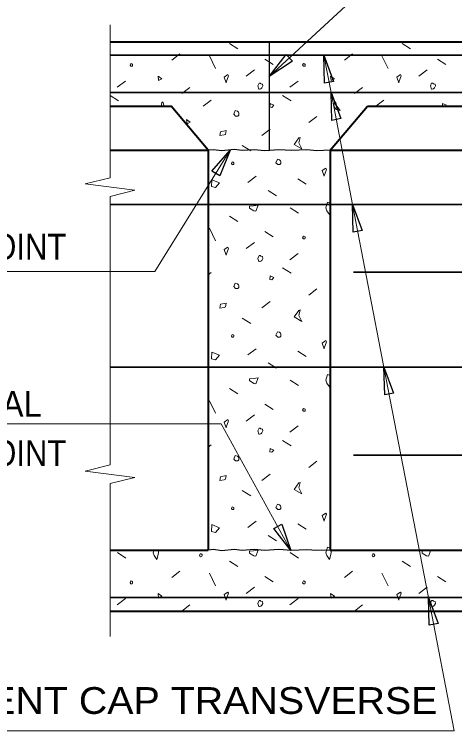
# Model space of a CAD drawing. Extents: x 0 to 34, y 0 to 23.4.
# Drawn here: x 12.452 to 15.025, y 15.614 to 19.798 of the extents above; entities that cross this region are included whole.
import ezdxf
from ezdxf.enums import TextEntityAlignment as Align

# ---------------------------------------------------------------- set-up
doc = ezdxf.new("R2010")
doc.units = 0
doc.header["$LTSCALE"] = 0.062
for name, color, linetype, lineweight in [('1', 7, 'Continuous', 40), ('3', 7, 'Continuous', 35), ('4', 7, 'Continuous', 13), ('7', 7, 'Continuous', 13)]:
    doc.layers.add(name, color=color, linetype=linetype, lineweight=lineweight)

msp = doc.modelspace()

# ---------------------------------------------------------------- linework, layer by layer
at = {"layer": '1', "lineweight": 13}
for p, q in [((13.0112, 18.84359), (13.0112, 19.73682)), ((13.0112, 17.16651), (13.0112, 18.73422)), ((13.0112, 16.16391), (13.0112, 17.05714))]:
    msp.add_line(p, q, dxfattribs=at)
at = {"layer": '1'}
for p, q in [((13.0112, 19.63786), (17.36536, 19.63786)), ((13.0112, 19.26182), (13.36745, 19.26182)), ((13.58516, 19.00453), (13.36745, 19.26182)), ((14.29766, 19.00453), (14.51536, 19.26182)), ((14.51536, 19.26182), (17.36536, 19.26182)), ((14.29766, 19.00667), (14.29766, 16.66911)), ((13.0112, 16.66911), (13.58516, 16.66911)), ((14.29766, 16.66911), (17.36536, 16.66911)), ((13.0112, 16.31286), (17.36536, 16.31286))]:
    msp.add_line(p, q, dxfattribs=at)
at = {"layer": '1', "lineweight": 25}
msp.add_line((13.94141, 19.63786), (13.94141, 19.00453), dxfattribs=at)
at = {"layer": '1'}
for points in [[(13.0112, 19.00453), (13.58516, 19.00453), (13.58516, 16.66911)], [(14.29766, 19.00453), (16.07891, 19.00453), (17.36536, 19.00453)]]:
    msp.add_lwpolyline(points, dxfattribs=at)
at = {"layer": '1', "lineweight": 25}
for points in [[(14.29766, 19.00453), (14.21839, 19.00125), (14.16151, 19.00667), (14.07125, 19.0025), (13.99667, 19.00693), (13.91625, 19.00151), (13.85344, 19.00714), (13.78281, 19.0025), (13.73573, 19.00786), (13.6651, 19.00078), (13.61604, 19.00714), (13.58516, 19.00453)], [(14.29766, 16.66911), (14.21839, 16.66583), (14.16151, 16.67125), (14.07125, 16.66708), (13.99667, 16.67151), (13.91625, 16.66609), (13.85344, 16.67172), (13.78281, 16.66708), (13.73573, 16.67245), (13.6651, 16.66536), (13.61604, 16.67172), (13.58516, 16.66911)]]:
    msp.add_lwpolyline(points, dxfattribs=at)
at = {"layer": '1', "lineweight": 13}
for points in [[(13.0112, 18.84359), (12.86536, 18.80714), (13.15703, 18.77068), (13.0112, 18.73422)], [(13.0112, 17.16651), (12.86536, 17.13005), (13.15703, 17.09359), (13.0112, 17.05714)]]:
    msp.add_lwpolyline(points, dxfattribs=at)
at = {"layer": '3'}
for p, q in [((13.0112, 19.5587), (17.36536, 19.5587)), ((13.0112, 19.34099), (17.36536, 19.34099)), ((17.36536, 18.68786), (13.0112, 18.68786)), ((17.36536, 18.29203), (14.43375, 18.29203)), ((17.36536, 17.73786), (13.0112, 17.73786)), ((17.36536, 17.22328), (14.43375, 17.22328)), ((13.0112, 16.39203), (17.36536, 16.39203))]:
    msp.add_line(p, q, dxfattribs=at)
at = {"layer": '4'}
for p, q in [((14.52495, 19.97521), (13.94141, 19.43542)), ((14.30255, 19.34099), (14.26052, 19.5587)), ((14.42844, 18.68786), (14.3025, 19.34099)), ((13.27292, 18.29536), (13.71349, 19.00453)), ((14.61161, 17.73786), (14.42839, 18.68786)), ((11.35625, 18.29536), (13.27292, 18.29536)), ((11.35625, 17.40693), (13.66078, 17.40693)), ((13.66078, 17.40693), (14.06828, 16.66724)), ((10.84479, 15.61406), (15.02104, 15.61406))]:
    msp.add_line(p, q, dxfattribs=at)
at = {"layer": '4', "lineweight": 25}
for points in [[(14.04073, 19.56365), (14.07698, 19.52448), (13.94141, 19.43542)], [(14.31698, 19.40661), (14.26464, 19.39656), (14.26052, 19.5587)], [(14.35896, 19.18891), (14.30661, 19.17885), (14.3025, 19.34099)], [(13.65172, 18.85453), (13.60641, 18.88271), (13.71349, 19.00453)], [(14.4849, 18.53583), (14.4325, 18.52573), (14.42839, 18.68786)], [(14.66802, 17.58578), (14.61568, 17.57573), (14.61156, 17.73786)], [(13.96771, 16.79453), (14.01443, 16.82026), (14.06828, 16.66724)], [(14.9275, 16.23995), (14.87516, 16.2299), (14.87104, 16.39203)]]:
    msp.add_lwpolyline(points, close=True, dxfattribs=at)
at = {"layer": '4'}
msp.add_lwpolyline([(15.02104, 15.61406), (14.87104, 16.39203), (14.61156, 17.73786)], dxfattribs=at)
at = {"layer": '7'}
for p, q in [((13.70901, 19.62688), (13.75849, 19.59563)), ((14.7174, 19.62688), (14.76688, 19.59563)), ((13.41995, 19.56719), (13.37182, 19.53057)), ((13.59151, 19.55609), (13.62818, 19.48255)), ((14.42833, 19.56719), (14.38021, 19.53057)), ((14.5999, 19.55609), (14.63656, 19.48255)), ((13.91536, 19.53656), (13.96484, 19.50531)), ((14.92375, 19.53656), (14.97323, 19.50531)), ((13.8549, 19.47344), (13.80677, 19.43682)), ((14.86328, 19.47344), (14.81516, 19.43682)), ((13.10115, 19.40844), (13.05302, 19.37182)), ((14.10953, 19.40844), (14.06141, 19.37182)), ((13.47828, 19.37151), (13.43016, 19.3349)), ((14.48667, 19.37151), (14.43854, 19.3349)), ((13.0112, 19.32448), (13.06068, 19.29323)), ((13.60255, 19.29755), (13.55443, 19.26094)), ((14.01958, 19.32448), (14.06906, 19.29323)), ((14.61094, 19.29755), (14.56396, 19.26182)), ((14.95427, 19.27714), (14.95359, 19.26182)), ((14.21984, 19.20198), (14.17172, 19.16536)), ((13.9463, 19.12729), (13.89818, 19.09068)), ((13.78328, 19.0312), (13.83281, 19)), ((13.86521, 18.85255), (13.81708, 18.81594)), ((14.10766, 18.8376), (14.15708, 18.80656)), ((13.93411, 18.76932), (13.98365, 18.73807)), ((14.06271, 18.66859), (14.11214, 18.63729)), ((14.29766, 18.69516), (14.2825, 18.70099)), ((13.70901, 18.61953), (13.75849, 18.58828)), ((13.59151, 18.54875), (13.62818, 18.47521)), ((13.91536, 18.52922), (13.96484, 18.49797)), ((13.8549, 18.46609), (13.80677, 18.42948)), ((14.10953, 18.40109), (14.06141, 18.36448)), ((13.60255, 18.29021), (13.58516, 18.27698)), ((14.01958, 18.31714), (14.06906, 18.28589)), ((14.21984, 18.19464), (14.17172, 18.15802)), ((13.9463, 18.11995), (13.89818, 18.08333)), ((13.78328, 18.02385), (13.83281, 17.99266)), ((13.86521, 17.84521), (13.81708, 17.80859)), ((14.10766, 17.83026), (14.15708, 17.79922)), ((13.93411, 17.76198), (13.98365, 17.73073)), ((14.06271, 17.66125), (14.11214, 17.62995)), ((14.29766, 17.68781), (14.2825, 17.69365)), ((13.70901, 17.61219), (13.75849, 17.58094)), ((13.59151, 17.54141), (13.62818, 17.46786)), ((13.91536, 17.52188), (13.96484, 17.49063)), ((13.8549, 17.45875), (13.80677, 17.42214)), ((14.10953, 17.39375), (14.06141, 17.35714)), ((13.60255, 17.28286), (13.58516, 17.26964)), ((14.01958, 17.30979), (14.06906, 17.27854)), ((14.21984, 17.18729), (14.17172, 17.15068)), ((13.9463, 17.1126), (13.89818, 17.07599)), ((13.78328, 17.01651), (13.83281, 16.98531)), ((13.86521, 16.83786), (13.81708, 16.80125)), ((14.10766, 16.82292), (14.15708, 16.79188)), ((13.93411, 16.75464), (13.98365, 16.72339)), ((13.05432, 16.65391), (13.10375, 16.6226)), ((14.06271, 16.65391), (14.11214, 16.6226)), ((14.29766, 16.68047), (14.2825, 16.6863)), ((13.70901, 16.60484), (13.75849, 16.57359)), ((14.7174, 16.60484), (14.76688, 16.57359)), ((13.41995, 16.54516), (13.37182, 16.50854)), ((13.59151, 16.53406), (13.62818, 16.46052)), ((14.42833, 16.54516), (14.38021, 16.50854)), ((14.5999, 16.53406), (14.63656, 16.46052)), ((13.91536, 16.51453), (13.96484, 16.48328)), ((14.92375, 16.51453), (14.97323, 16.48328)), ((13.8549, 16.45141), (13.80677, 16.41479)), ((14.86328, 16.45141), (14.81516, 16.41479)), ((13.10115, 16.38641), (13.05302, 16.34979)), ((14.10953, 16.38641), (14.06141, 16.34979)), ((13.47828, 16.34948), (13.43016, 16.31286)), ((14.48667, 16.34948), (14.43854, 16.31286))]:
    msp.add_line(p, q, dxfattribs=at)
for points in [[(13.1326, 19.51047), (13.12797, 19.50031), (13.13339, 19.49469), (13.14, 19.49469), (13.14271, 19.49766), (13.14271, 19.50307), (13.14182, 19.50573), (13.13896, 19.5087)], [(14.14099, 19.51047), (14.13635, 19.50031), (14.14177, 19.49469), (14.14839, 19.49469), (14.15109, 19.49766), (14.15109, 19.50307), (14.15021, 19.50573), (14.14734, 19.5087)], [(13.29151, 19.43672), (13.29521, 19.41089), (13.3137, 19.42198)], [(13.67755, 19.4313), (13.68896, 19.39807), (13.68896, 19.40167), (13.70365, 19.43865), (13.6999, 19.44599)], [(14.2999, 19.43672), (14.30359, 19.41089), (14.32208, 19.42198)], [(14.68594, 19.4313), (14.69734, 19.39807), (14.69734, 19.40167), (14.71203, 19.43865), (14.70828, 19.44599)], [(13.87417, 19.37958), (13.88, 19.36115), (13.88531, 19.36115), (13.89281, 19.36297), (13.89823, 19.36833), (13.90359, 19.37958), (13.90208, 19.39052), (13.89281, 19.39245), (13.88891, 19.39625), (13.88156, 19.39625)], [(14.88255, 19.37958), (14.88839, 19.36115), (14.8937, 19.36115), (14.9012, 19.36297), (14.90661, 19.36833), (14.91198, 19.37958), (14.91047, 19.39052), (14.9012, 19.39245), (14.89729, 19.39625), (14.88995, 19.39625)], [(13.94589, 19.27714), (13.945, 19.25734), (13.95693, 19.25458), (13.96844, 19.26792)], [(14.32234, 19.2826), (14.31828, 19.26187), (14.33203, 19.24156), (14.35505, 19.23703), (14.33667, 19.26141), (14.3288, 19.28672)], [(13.74292, 19.23552), (13.73365, 19.21531), (13.74448, 19.20406), (13.75771, 19.20406), (13.76313, 19.20995), (13.76313, 19.22073), (13.7613, 19.22604), (13.75557, 19.23198)], [(13.45813, 19.18359), (13.46182, 19.15776), (13.48031, 19.16885)], [(13.65594, 19.11193), (13.65224, 19.0899), (13.67807, 19.09359), (13.68536, 19.09719), (13.68906, 19.11932)], [(14.11323, 19.07625), (14.0875, 19.03771), (14.13078, 19.01177), (14.115, 19.04682), (14.12167, 19.07891)], [(13.72448, 18.93615), (13.71984, 18.92604), (13.72526, 18.92042), (13.73188, 18.92042), (13.73458, 18.92333), (13.73458, 18.92875), (13.7337, 18.93141), (13.73083, 18.93438)], [(13.98896, 18.95177), (13.97969, 18.93156), (13.99052, 18.92031), (14.00375, 18.92031), (14.00917, 18.9262), (14.00917, 18.93698), (14.00734, 18.94229), (14.00161, 18.94823)], [(14.25016, 18.88536), (14.26151, 18.85214), (14.26151, 18.85568), (14.2763, 18.89271), (14.27255, 18.90005)], [(13.60526, 18.83224), (13.60349, 18.79266), (13.6274, 18.78708), (13.65042, 18.8138)], [(13.84875, 18.67906), (13.82667, 18.67719), (13.82667, 18.66615), (13.85063, 18.64964), (13.86359, 18.64776), (13.87651, 18.68271)], [(14.14099, 18.50313), (14.13635, 18.49297), (14.14177, 18.48734), (14.14839, 18.48734), (14.15109, 18.49031), (14.15109, 18.49573), (14.15021, 18.49839), (14.14734, 18.50135)], [(13.67755, 18.42396), (13.68896, 18.39073), (13.68896, 18.39432), (13.70365, 18.4313), (13.6999, 18.43865)], [(13.87417, 18.37224), (13.88, 18.3538), (13.88531, 18.3538), (13.89281, 18.35562), (13.89823, 18.36099), (13.90359, 18.37224), (13.90208, 18.38318), (13.89281, 18.3851), (13.88891, 18.38891), (13.88156, 18.38891)], [(13.94589, 18.26979), (13.945, 18.25), (13.95693, 18.24724), (13.96844, 18.26057)], [(13.74292, 18.22818), (13.73365, 18.20797), (13.74448, 18.19672), (13.75771, 18.19672), (13.76313, 18.2026), (13.76313, 18.21339), (13.7613, 18.2187), (13.75557, 18.22464)], [(13.65594, 18.10458), (13.65224, 18.08255), (13.67807, 18.08625), (13.68536, 18.08984), (13.68906, 18.11198)], [(14.11323, 18.06891), (14.0875, 18.03036), (14.13078, 18.00443), (14.115, 18.03948), (14.12167, 18.07156)], [(13.72448, 17.9288), (13.71984, 17.9187), (13.72526, 17.91307), (13.73188, 17.91307), (13.73458, 17.91599), (13.73458, 17.92141), (13.7337, 17.92406), (13.73083, 17.92703)], [(13.98896, 17.94443), (13.97969, 17.92422), (13.99052, 17.91297), (14.00375, 17.91297), (14.00917, 17.91885), (14.00917, 17.92964), (14.00734, 17.93495), (14.00161, 17.94089)], [(14.25016, 17.87802), (14.26151, 17.84479), (14.26151, 17.84833), (14.2763, 17.88536), (14.27255, 17.89271)], [(13.60526, 17.8249), (13.60349, 17.78531), (13.6274, 17.77974), (13.65042, 17.80646)], [(13.84875, 17.67172), (13.82667, 17.66984), (13.82667, 17.6588), (13.85063, 17.64229), (13.86359, 17.64042), (13.87651, 17.67536)], [(14.14099, 17.49578), (14.13635, 17.48563), (14.14177, 17.48), (14.14839, 17.48), (14.15109, 17.48297), (14.15109, 17.48839), (14.15021, 17.49104), (14.14734, 17.49401)], [(13.67755, 17.41661), (13.68896, 17.38339), (13.68896, 17.38698), (13.70365, 17.42396), (13.6999, 17.4313)], [(13.87417, 17.3649), (13.88, 17.34646), (13.88531, 17.34646), (13.89281, 17.34828), (13.89823, 17.35365), (13.90359, 17.3649), (13.90208, 17.37583), (13.89281, 17.37776), (13.88891, 17.38156), (13.88156, 17.38156)], [(13.94589, 17.26245), (13.945, 17.24266), (13.95693, 17.2399), (13.96844, 17.25323)], [(13.74292, 17.22083), (13.73365, 17.20063), (13.74448, 17.18938), (13.75771, 17.18938), (13.76313, 17.19526), (13.76313, 17.20604), (13.7613, 17.21135), (13.75557, 17.21729)], [(13.65594, 17.09724), (13.65224, 17.07521), (13.67807, 17.07891), (13.68536, 17.0825), (13.68906, 17.10464)], [(14.11323, 17.06156), (14.0875, 17.02302), (14.13078, 16.99708), (14.115, 17.03214), (14.12167, 17.06422)], [(13.72448, 16.92146), (13.71984, 16.91135), (13.72526, 16.90573), (13.73188, 16.90573), (13.73458, 16.90865), (13.73458, 16.91406), (13.7337, 16.91672), (13.73083, 16.91969)], [(13.98896, 16.93708), (13.97969, 16.91688), (13.99052, 16.90563), (14.00375, 16.90563), (14.00917, 16.91151), (14.00917, 16.92229), (14.00734, 16.9276), (14.00161, 16.93354)], [(14.25016, 16.87068), (14.26151, 16.83745), (14.26151, 16.84099), (14.2763, 16.87802), (14.27255, 16.88536)], [(13.60526, 16.81755), (13.60349, 16.77797), (13.6274, 16.7724), (13.65042, 16.79911)], [(13.84875, 16.66437), (13.82667, 16.6625), (13.82667, 16.65146), (13.85063, 16.63495), (13.86359, 16.63307), (13.87651, 16.66802)], [(14.85714, 16.66437), (14.83505, 16.6625), (14.83505, 16.65146), (14.85901, 16.63495), (14.87198, 16.63307), (14.8849, 16.66802)], [(13.53453, 16.63906), (13.53745, 16.62984), (13.5401, 16.62984), (13.54385, 16.63078), (13.54656, 16.63344), (13.54922, 16.63906), (13.54849, 16.64458), (13.54385, 16.64552), (13.54188, 16.64745), (13.53823, 16.64745)], [(14.54292, 16.63906), (14.54583, 16.62984), (14.54849, 16.62984), (14.55224, 16.63078), (14.55495, 16.63344), (14.5576, 16.63906), (14.55688, 16.64458), (14.55224, 16.64552), (14.55026, 16.64745), (14.54661, 16.64745)], [(13.1326, 16.48844), (13.12797, 16.47828), (13.13339, 16.47266), (13.14, 16.47266), (13.14271, 16.47563), (13.14271, 16.48104), (13.14182, 16.4837), (13.13896, 16.48667)], [(14.14099, 16.48844), (14.13635, 16.47828), (14.14177, 16.47266), (14.14839, 16.47266), (14.15109, 16.47563), (14.15109, 16.48104), (14.15021, 16.4837), (14.14734, 16.48667)], [(13.29151, 16.41469), (13.29521, 16.38885), (13.3137, 16.39995)], [(13.67755, 16.40927), (13.68896, 16.37604), (13.68896, 16.37964), (13.70365, 16.41661), (13.6999, 16.42396)], [(14.2999, 16.41469), (14.30359, 16.38885), (14.32208, 16.39995)], [(14.68594, 16.40927), (14.69734, 16.37604), (14.69734, 16.37964), (14.71203, 16.41661), (14.70828, 16.42396)], [(13.87417, 16.35755), (13.88, 16.33911), (13.88531, 16.33911), (13.89281, 16.34094), (13.89823, 16.3463), (13.90359, 16.35755), (13.90208, 16.36849), (13.89281, 16.37042), (13.88891, 16.37422), (13.88156, 16.37422)], [(14.88255, 16.35755), (14.88839, 16.33911), (14.8937, 16.33911), (14.9012, 16.34094), (14.90661, 16.3463), (14.91198, 16.35755), (14.91047, 16.36849), (14.9012, 16.37042), (14.89729, 16.37422), (14.88995, 16.37422)]]:
    msp.add_lwpolyline(points, close=True, dxfattribs=at)
for points in [[(13.31396, 19.2826), (13.3099, 19.26187), (13.30995, 19.26182)], [(13.32818, 19.26182), (13.32042, 19.28672), (13.31396, 19.2826)], [(14.97156, 19.26182), (14.97682, 19.26792), (14.95427, 19.27714)], [(14.2825, 18.70099), (14.2713, 18.66786), (14.27698, 18.6513), (14.29354, 18.62917), (14.29766, 18.64568)], [(14.2825, 17.69365), (14.2713, 17.66052), (14.27698, 17.64396), (14.29354, 17.62182), (14.29766, 17.63833)], [(13.26828, 16.66911), (13.26292, 16.65318), (13.26859, 16.63661), (13.28516, 16.61448), (13.2925, 16.64396), (13.29667, 16.66911)], [(14.2825, 16.6863), (14.2713, 16.65318), (14.27698, 16.63661), (14.29354, 16.61448), (14.30089, 16.64396), (14.30505, 16.66911)]]:
    msp.add_lwpolyline(points, dxfattribs=at)

# ---------------------------------------------------------------- texts
at = {"layer": '4'}
for s, width, p in [('CONST. JOINT', 0.9, (11.49875, 18.36594)), ('OPTIONAL', 0.95, (11.64635, 17.44729)), ('CONST. JOINT', 0.9, (11.4987, 17.16021))]:
    msp.add_text(s, height=0.1504, dxfattribs=dict(at, width=width)).set_placement(p)
at = {"layer": '4', "width": 1.1}
msp.add_text('SLAB AND BENT CAP TRANSVERSE', height=0.1563, dxfattribs=at).set_placement((14.92427, 15.71203), align=Align.RIGHT)

doc.saveas('drawing.dxf')
